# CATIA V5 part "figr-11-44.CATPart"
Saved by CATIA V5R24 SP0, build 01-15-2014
Part number: Part1
Bounding box of the stored display mesh (mm): x -59 to 59, y -60 to 60, z 0 to 39.8
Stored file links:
  D:\KAVITA\CATIA V5-6R2014 Project_ Kavita\CATIA V5-6R2014_partfiles\Partfiles\c11_catia_v5-6r2014_prt\figr-11-44.CATPart
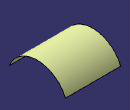
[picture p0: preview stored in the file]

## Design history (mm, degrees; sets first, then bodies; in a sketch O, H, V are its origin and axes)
AxisSystem1: origin (0, 0, 0), X (1, 0, 0), Y (0, 1, 0), Z (0, 0, 1)
AxisSystem2: origin (0, 150, -30), X (1, 0, 0), Y (0, 1, 0), Z (0, 0, 1)
Set1
  Extrude1: Element1 Sketch2, Lim1 59, Lim2 59, Direction yz-plane
  Sketch1 on yz-plane, origin (0, 0, 0), H (0, 1, 0), V (0, 0, 1)
    point P1 (150, -30)
  AxisToAxis1: ToTransfor Extrude1, AxisOrigin AxisSystem1, Axis AxisSystem2
Body1 (main body)
  Sketch2 on yz-plane, origin (0, 0, 0), H (0, 1, 0), V (0, 0, 1)
    arc A1 centre (0, -25) radius 65 from (-60, 0) to (60, 0) cw
    point P2 (-60, 0)
    point P3 (60, 0)
    coincidence: P2 H, P3 H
